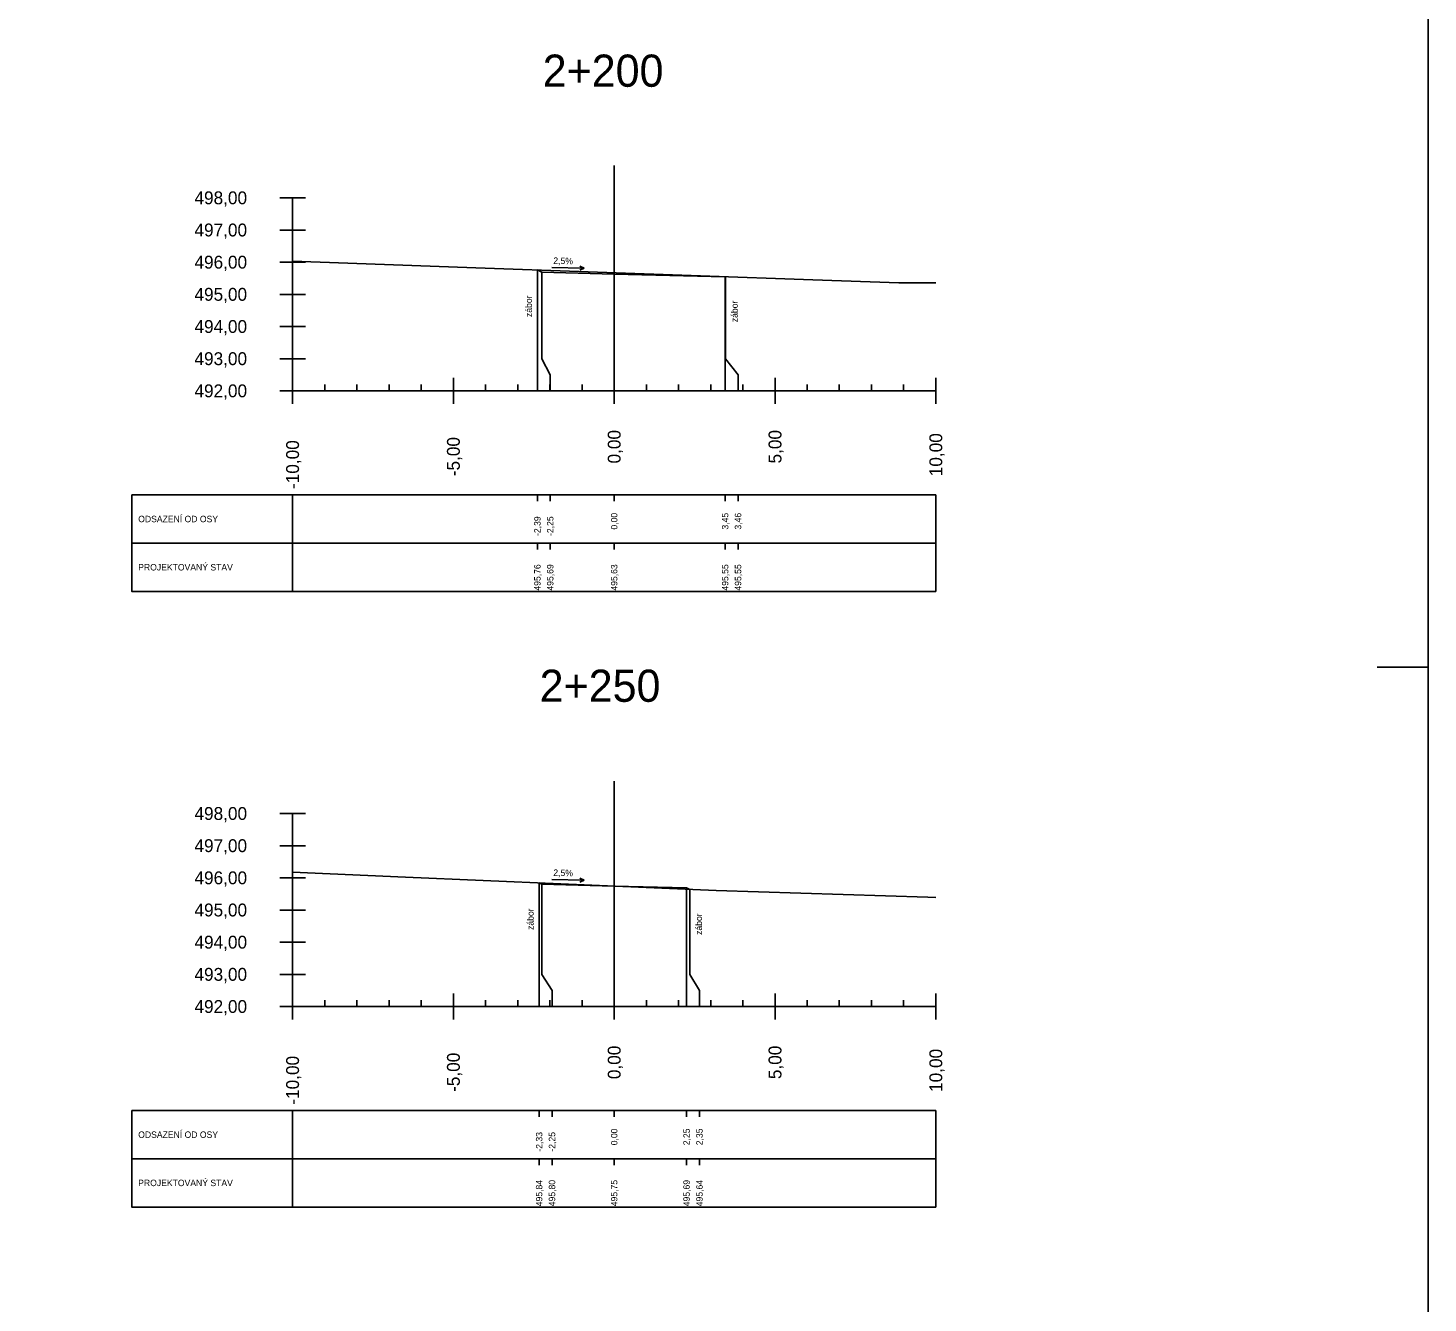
# Model space of a CAD drawing. Extents: x -631407 to -631215, y -1089700 to -1088598.
# Drawn here: x -631258.91 to -631215.38, y -1089231.17 to -1089191.53 of the extents above; entities that cross this region are included whole.
import ezdxf

# ---------------------------------------------------------------- set-up
doc = ezdxf.new("R2010")
doc.units = 0
for name, color, linetype in [('08_LEGENDA_HV', 7, 'Continuous'), ('59', 7, 'Continuous'), ('DTM-Breaklines', 7, 'Continuous'), ('NIVELETA_VYSKY', 7, 'Continuous'), ('REZ_BODY', 7, 'Continuous'), ('REZ_ODSTUPY', 7, 'Continuous'), ('REZ_POPIS', 7, 'Continuous'), ('REZ_RAMY', 7, 'Continuous'), ('REZ_STANICENI', 7, 'Continuous'), ('REZ_SVISLE', 7, 'Continuous'), ('REZ_TENKA', 7, 'Continuous'), ('REZ_TLUSTA', 7, 'Continuous'), ('TABULKA_POPIS', 7, 'Continuous'), ('TEREN', 7, 'Continuous'), ('zábor', 7, 'Continuous')]:
    doc.layers.add(name, color=color, linetype=linetype)

msp = doc.modelspace()

# ---------------------------------------------------------------- linework, layer by layer
at = {"layer": '08_LEGENDA_HV'}
msp.add_lwpolyline([(-631215.384, -1089270.801), (-631215.384, -1089110.964), (-631407.014, -1089110.964), (-631407.014, -1089270.801)], close=True, dxfattribs=at)
at = {"layer": '59'}
for p, q in [((-631251.088, -1089196.81), (-631250.288, -1089196.81)), ((-631250.688, -1089196.81), (-631250.688, -1089202.81)), ((-631251.088, -1089197.81), (-631250.288, -1089197.81)), ((-631251.088, -1089198.81), (-631250.288, -1089198.81)), ((-631251.088, -1089199.81), (-631250.288, -1089199.81)), ((-631251.088, -1089200.81), (-631250.288, -1089200.81)), ((-631251.088, -1089201.81), (-631250.288, -1089201.81)), ((-631251.088, -1089202.81), (-631250.288, -1089202.81)), ((-631251.088, -1089215.949), (-631250.288, -1089215.949)), ((-631250.688, -1089215.949), (-631250.688, -1089221.949)), ((-631251.088, -1089216.949), (-631250.288, -1089216.949)), ((-631251.088, -1089217.949), (-631250.288, -1089217.949)), ((-631251.088, -1089218.949), (-631250.288, -1089218.949)), ((-631251.088, -1089219.949), (-631250.288, -1089219.949)), ((-631251.088, -1089220.949), (-631250.288, -1089220.949)), ((-631251.088, -1089221.949), (-631250.288, -1089221.949))]:
    msp.add_line(p, q, dxfattribs=at)
at = {"layer": 'DTM-Breaklines'}
msp.add_line((-631216.965, -1089211.401), (-631215.384, -1089211.401), dxfattribs=at)
at = {"layer": 'REZ_RAMY'}
for p, q in [((-631255.688, -1089206.044), (-631255.688, -1089209.044)), ((-631250.688, -1089206.044), (-631250.688, -1089209.044)), ((-631243.077, -1089206.244), (-631243.077, -1089206.044)), ((-631242.677, -1089206.244), (-631242.677, -1089206.044)), ((-631240.688, -1089206.244), (-631240.688, -1089206.044)), ((-631237.238, -1089206.244), (-631237.238, -1089206.044)), ((-631236.838, -1089206.244), (-631236.838, -1089206.044)), ((-631255.688, -1089207.544), (-631230.688, -1089207.544)), ((-631243.077, -1089207.744), (-631243.077, -1089207.544)), ((-631242.677, -1089207.744), (-631242.677, -1089207.544)), ((-631240.688, -1089207.744), (-631240.688, -1089207.544)), ((-631237.238, -1089207.744), (-631237.238, -1089207.544)), ((-631236.838, -1089207.744), (-631236.838, -1089207.544)), ((-631255.688, -1089225.183), (-631255.688, -1089228.183)), ((-631250.688, -1089225.183), (-631250.688, -1089228.183)), ((-631243.022, -1089225.383), (-631243.022, -1089225.183)), ((-631242.622, -1089225.383), (-631242.622, -1089225.183)), ((-631240.688, -1089225.383), (-631240.688, -1089225.183)), ((-631238.438, -1089225.383), (-631238.438, -1089225.183)), ((-631238.038, -1089225.383), (-631238.038, -1089225.183)), ((-631255.688, -1089226.683), (-631230.688, -1089226.683)), ((-631243.022, -1089226.883), (-631243.022, -1089226.683)), ((-631242.622, -1089226.883), (-631242.622, -1089226.683)), ((-631240.688, -1089226.883), (-631240.688, -1089226.683)), ((-631238.438, -1089226.883), (-631238.438, -1089226.683)), ((-631238.038, -1089226.883), (-631238.038, -1089226.683))]:
    msp.add_line(p, q, dxfattribs=at)
for points in [[(-631255.688, -1089206.044), (-631255.688, -1089209.044), (-631230.688, -1089209.044), (-631230.688, -1089206.044)], [(-631255.688, -1089225.183), (-631255.688, -1089228.183), (-631230.688, -1089228.183), (-631230.688, -1089225.183)]]:
    msp.add_lwpolyline(points, close=True, dxfattribs=at)
at = {"layer": 'REZ_SVISLE'}
for points in [[(-631243.077, -1089199.053), (-631243.077, -1089201.81), (-631243.077, -1089202.31), (-631243.077, -1089202.81)], [(-631242.938, -1089199.123), (-631242.938, -1089201.81), (-631242.677, -1089202.31), (-631242.677, -1089202.81)], [(-631240.688, -1089199.179), (-631240.688, -1089201.81), (-631240.688, -1089202.31), (-631240.688, -1089202.81)], [(-631237.238, -1089199.265), (-631237.238, -1089201.81), (-631237.238, -1089202.31), (-631237.238, -1089202.81)], [(-631237.231, -1089199.262), (-631237.231, -1089201.81), (-631236.838, -1089202.31), (-631236.838, -1089202.81)], [(-631243.022, -1089218.105), (-631243.022, -1089220.949), (-631243.022, -1089221.449), (-631243.022, -1089221.949)], [(-631242.938, -1089218.147), (-631242.938, -1089220.949), (-631242.622, -1089221.449), (-631242.622, -1089221.949)], [(-631240.688, -1089218.204), (-631240.688, -1089220.949), (-631240.688, -1089221.449), (-631240.688, -1089221.949)], [(-631238.438, -1089218.26), (-631238.438, -1089220.949), (-631238.438, -1089221.449), (-631238.438, -1089221.949)], [(-631238.34, -1089218.309), (-631238.34, -1089220.949), (-631238.038, -1089221.449), (-631238.038, -1089221.949)]]:
    msp.add_lwpolyline(points, dxfattribs=at)
at = {"layer": 'REZ_TENKA'}
for p, q in [((-631249.688, -1089202.81), (-631249.688, -1089202.61)), ((-631248.688, -1089202.81), (-631248.688, -1089202.61)), ((-631247.688, -1089202.81), (-631247.688, -1089202.61)), ((-631246.688, -1089202.81), (-631246.688, -1089202.61)), ((-631244.688, -1089202.81), (-631244.688, -1089202.61)), ((-631243.688, -1089202.81), (-631243.688, -1089202.61)), ((-631242.688, -1089202.81), (-631242.688, -1089202.61)), ((-631241.688, -1089202.81), (-631241.688, -1089202.61)), ((-631239.688, -1089202.81), (-631239.688, -1089202.61)), ((-631238.688, -1089202.81), (-631238.688, -1089202.61)), ((-631237.688, -1089202.81), (-631237.688, -1089202.61)), ((-631236.688, -1089202.81), (-631236.688, -1089202.61)), ((-631234.688, -1089202.81), (-631234.688, -1089202.61)), ((-631233.688, -1089202.81), (-631233.688, -1089202.61)), ((-631232.688, -1089202.81), (-631232.688, -1089202.61)), ((-631231.688, -1089202.81), (-631231.688, -1089202.61)), ((-631249.688, -1089221.949), (-631249.688, -1089221.749)), ((-631248.688, -1089221.949), (-631248.688, -1089221.749)), ((-631247.688, -1089221.949), (-631247.688, -1089221.749)), ((-631246.688, -1089221.949), (-631246.688, -1089221.749)), ((-631244.688, -1089221.949), (-631244.688, -1089221.749)), ((-631243.688, -1089221.949), (-631243.688, -1089221.749)), ((-631242.688, -1089221.949), (-631242.688, -1089221.749)), ((-631241.688, -1089221.949), (-631241.688, -1089221.749)), ((-631239.688, -1089221.949), (-631239.688, -1089221.749)), ((-631238.688, -1089221.949), (-631238.688, -1089221.749)), ((-631237.688, -1089221.949), (-631237.688, -1089221.749)), ((-631236.688, -1089221.949), (-631236.688, -1089221.749)), ((-631234.688, -1089221.949), (-631234.688, -1089221.749)), ((-631233.688, -1089221.949), (-631233.688, -1089221.749)), ((-631232.688, -1089221.949), (-631232.688, -1089221.749)), ((-631231.688, -1089221.949), (-631231.688, -1089221.749))]:
    msp.add_line(p, q, dxfattribs=at)
at = {"layer": 'REZ_TLUSTA'}
for p, q in [((-631240.688, -1089195.81), (-631240.688, -1089202.81)), ((-631250.688, -1089203.21), (-631250.688, -1089202.41)), ((-631245.688, -1089203.21), (-631245.688, -1089202.41)), ((-631240.688, -1089203.21), (-631240.688, -1089202.41)), ((-631235.688, -1089203.21), (-631235.688, -1089202.41)), ((-631230.688, -1089203.21), (-631230.688, -1089202.41)), ((-631250.688, -1089202.81), (-631230.688, -1089202.81)), ((-631240.688, -1089214.949), (-631240.688, -1089221.949)), ((-631250.688, -1089222.349), (-631250.688, -1089221.549)), ((-631245.688, -1089222.349), (-631245.688, -1089221.549)), ((-631240.688, -1089222.349), (-631240.688, -1089221.549)), ((-631235.688, -1089222.349), (-631235.688, -1089221.549)), ((-631230.688, -1089222.349), (-631230.688, -1089221.549)), ((-631250.688, -1089221.949), (-631230.688, -1089221.949))]:
    msp.add_line(p, q, dxfattribs=at)
at = {"layer": 'TEREN'}
for points in [[(-631250.688, -1089198.782), (-631248.969, -1089198.838), (-631244.99, -1089198.985), (-631234.517, -1089199.359), (-631231.843, -1089199.449), (-631230.688, -1089199.451)], [(-631243.077, -1089199.053), (-631242.938, -1089199.123), (-631240.688, -1089199.179), (-631237.238, -1089199.265), (-631237.231, -1089199.262)], [(-631250.688, -1089217.768), (-631247.181, -1089217.924), (-631237.519, -1089218.345), (-631230.941, -1089218.552), (-631230.688, -1089218.564)], [(-631243.022, -1089218.105), (-631242.938, -1089218.147), (-631240.688, -1089218.204), (-631238.438, -1089218.26), (-631238.34, -1089218.309)]]:
    msp.add_lwpolyline(points, dxfattribs=at)
at = {"layer": 'zábor'}
for p, q in [((-631241.621, -1089198.999), (-631241.757, -1089198.935)), ((-631241.621, -1089198.999), (-631242.629, -1089198.974)), ((-631241.621, -1089198.999), (-631241.76, -1089199.057)), ((-631241.621, -1089218.024), (-631242.629, -1089217.999)), ((-631241.621, -1089218.024), (-631241.76, -1089218.082)), ((-631241.621, -1089218.024), (-631241.757, -1089217.959))]:
    msp.add_line(p, q, dxfattribs=at)

# ---------------------------------------------------------------- texts
at = {"layer": 'NIVELETA_VYSKY'}
for s, p in [('495,76', (-631242.977, -1089209.02)), ('495,69', (-631242.577, -1089209.02)), ('495,63', (-631240.588, -1089209.02)), ('495,55', (-631237.138, -1089209.02)), ('495,55', (-631236.738, -1089209.02)), ('495,84', (-631242.922, -1089228.158)), ('495,80', (-631242.522, -1089228.158)), ('495,75', (-631240.588, -1089228.158)), ('495,69', (-631238.338, -1089228.158)), ('495,64', (-631237.938, -1089228.158))]:
    msp.add_text(s, height=0.2, rotation=90, dxfattribs=at).set_placement(p)
at = {"layer": 'REZ_BODY'}
for s, p in [('-2,39', (-631242.977, -1089207.321)), ('-2,25', (-631242.577, -1089207.321)), ('0,00', (-631240.588, -1089207.123)), ('3,45', (-631237.138, -1089207.123)), ('3,46', (-631236.738, -1089207.123)), ('-2,33', (-631242.922, -1089226.46)), ('-2,25', (-631242.522, -1089226.46)), ('0,00', (-631240.588, -1089226.262)), ('2,25', (-631238.338, -1089226.262)), ('2,35', (-631237.938, -1089226.262))]:
    msp.add_text(s, height=0.2, rotation=90, dxfattribs=at).set_placement(p)
at = {"layer": 'REZ_ODSTUPY'}
for s, p in [('0,00', (-631240.488, -1089205.068)), ('5,00', (-631235.488, -1089205.068)), ('10,00', (-631230.488, -1089205.465)), ('-10,00', (-631250.488, -1089205.862)), ('-5,00', (-631245.488, -1089205.465)), ('0,00', (-631240.488, -1089224.207)), ('5,00', (-631235.488, -1089224.207)), ('10,00', (-631230.488, -1089224.604)), ('-10,00', (-631250.488, -1089225.001)), ('-5,00', (-631245.488, -1089224.604))]:
    msp.add_text(s, height=0.4, rotation=90, dxfattribs=at).set_placement(p)
at = {"layer": 'REZ_POPIS'}
for s, p in [('498,00', (-631253.739, -1089197.01)), ('497,00', (-631253.739, -1089198.01)), ('496,00', (-631253.739, -1089199.01)), ('495,00', (-631253.739, -1089200.01)), ('494,00', (-631253.739, -1089201.01)), ('493,00', (-631253.739, -1089202.01)), ('492,00', (-631253.739, -1089203.01)), ('498,00', (-631253.739, -1089216.149)), ('497,00', (-631253.739, -1089217.149)), ('496,00', (-631253.739, -1089218.149)), ('495,00', (-631253.739, -1089219.149)), ('494,00', (-631253.739, -1089220.149)), ('493,00', (-631253.739, -1089221.149)), ('492,00', (-631253.739, -1089222.149))]:
    msp.add_text(s, height=0.4, dxfattribs=at).set_placement(p)
at = {"layer": 'REZ_STANICENI'}
for s, p in [('2+200', (-631242.911, -1089193.357)), ('2+250', (-631243.006, -1089212.477))]:
    msp.add_text(s, height=1, dxfattribs=at).set_placement(p)
at = {"layer": 'TABULKA_POPIS'}
for s, p in [('ODSAZENÍ OD OSY', (-631255.488, -1089206.894)), ('PROJEKTOVANÝ STAV', (-631255.488, -1089208.394)), ('ODSAZENÍ OD OSY', (-631255.488, -1089226.033)), ('PROJEKTOVANÝ STAV', (-631255.488, -1089227.533))]:
    msp.add_text(s, height=0.2, dxfattribs=at).set_placement(p)
at = {"layer": 'zábor'}
for s, rotation, p in [('2,5%', 358.5679, (-631242.584, -1089198.862)), ('zábor', 90, (-631243.247, -1089200.516)), ('zábor', 90, (-631236.848, -1089200.676)), ('2,5%', 358.5679, (-631242.584, -1089217.887)), ('zábor', 90, (-631243.193, -1089219.568)), ('zábor', 90, (-631237.957, -1089219.723))]:
    msp.add_text(s, height=0.2, rotation=rotation, dxfattribs=at).set_placement(p)

doc.saveas('drawing.dxf')
